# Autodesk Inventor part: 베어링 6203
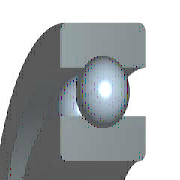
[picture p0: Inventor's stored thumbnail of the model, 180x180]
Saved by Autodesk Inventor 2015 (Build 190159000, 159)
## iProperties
IsCustomPart: 0
Created: 2014-10
Part Number: 베어링 6203
Material: 알루미늄 6061
Description: 깊은 그루브 볼 베어링
Document SubType Name: Modeling
Standard: KS B 2023
Designer: KYOUNG IL JANG
Standards Organization: KS
Language: ko-KR
Size Designation: 6203 - 17 x 40 x 12
Categories: <MemberInstance><Categories><Category DisplayName="샤프트 부품" InternalName="7f7aeb1f-a693-4053-b835-cee3144e0d98" Mnemonic="SHFT"><Category DisplayName="베어링" Inter
Density: 2.71 g/cm^3
Mass: 22.4044 g
Surface Area: 64.3582 cm^2
Volume: 8.26729 cm^3
Appearance: Aluminum - Flat
Author: SeoGD™ [www.esajin.kr]
Revision Number: 1
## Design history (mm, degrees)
sketch "스케치" dims "d0" = 5.98 (= -0.26 x WD + 0.26 x BD)
  geometry: L1 (3.01, 14.25)-(8.99, 14.25); L2 (6, 14.25)-(6, 11.26); L3 (6, 14.25)-(6, 17.24); L4 (3.778, 12.249)-(0, 12.249); L5 (0, 8.5)-(12, 8.5); L6 (3.778, 16.251)-(0, 16.251); L7 (0, 20)-(12, 20); L8 (12, 8.5)-(12, 12.249); L9 (8.222, 12.249)-(12, 12.249); L10 (8.222, 16.251)-(12, 16.251); L11 (12, 20)-(12, 16.251); L12 (-1.4, 0)-(8.4, 0) reference; L13 (0, -0.3)-(0, 5.3) reference
  constraints: 22 end point, 4 point on line, 2 collinear, 2 perpendicular, 2 symmetric about line, 1 midpoint, 1 parallel, 14 other
  dimensions: "d9" = 17 diameter of L5 L12 (= WD); "d11" = 40 diameter of L7 L12 (= BD); "d12" = 12 distance between parallel lines of L8 L13 (= KB); "d13" = 24.498 diameter of L9 L12 (= 0.326 x BD + 0.674 x WD)
revolve "본체" stored, may be unused: angle "d6" = 90 deg
revolve "볼" stored, may be unused: angle "d7" = 90 deg
pattern_circular "IDS_ARRAYBALL[SIMPL:T]" dims angle "d3" = 360 deg
body "Solid1"
fillet "모깎기1" dims "d1" = 0.6 (= KRS)
other parameters: "WD" = 17 [user parameter; used in 5 equation terms], "BD" = 40 [user parameter; used in 5 equation terms], "KB" = 12 [user parameter; used in 1 equation term], "KRS" = 0.6 [user parameter; used in 1 equation term], "d4" = 0, "d5" = 0, "d8" = 0, "d14" = 0, "d15" = 0, "BBA" = 0 [user parameter], "BC0" = 4750000 [user parameter], "BC" = 9560000 [user parameter], "WR" = 8.5 (= 0.5 x WD) [user parameter]
